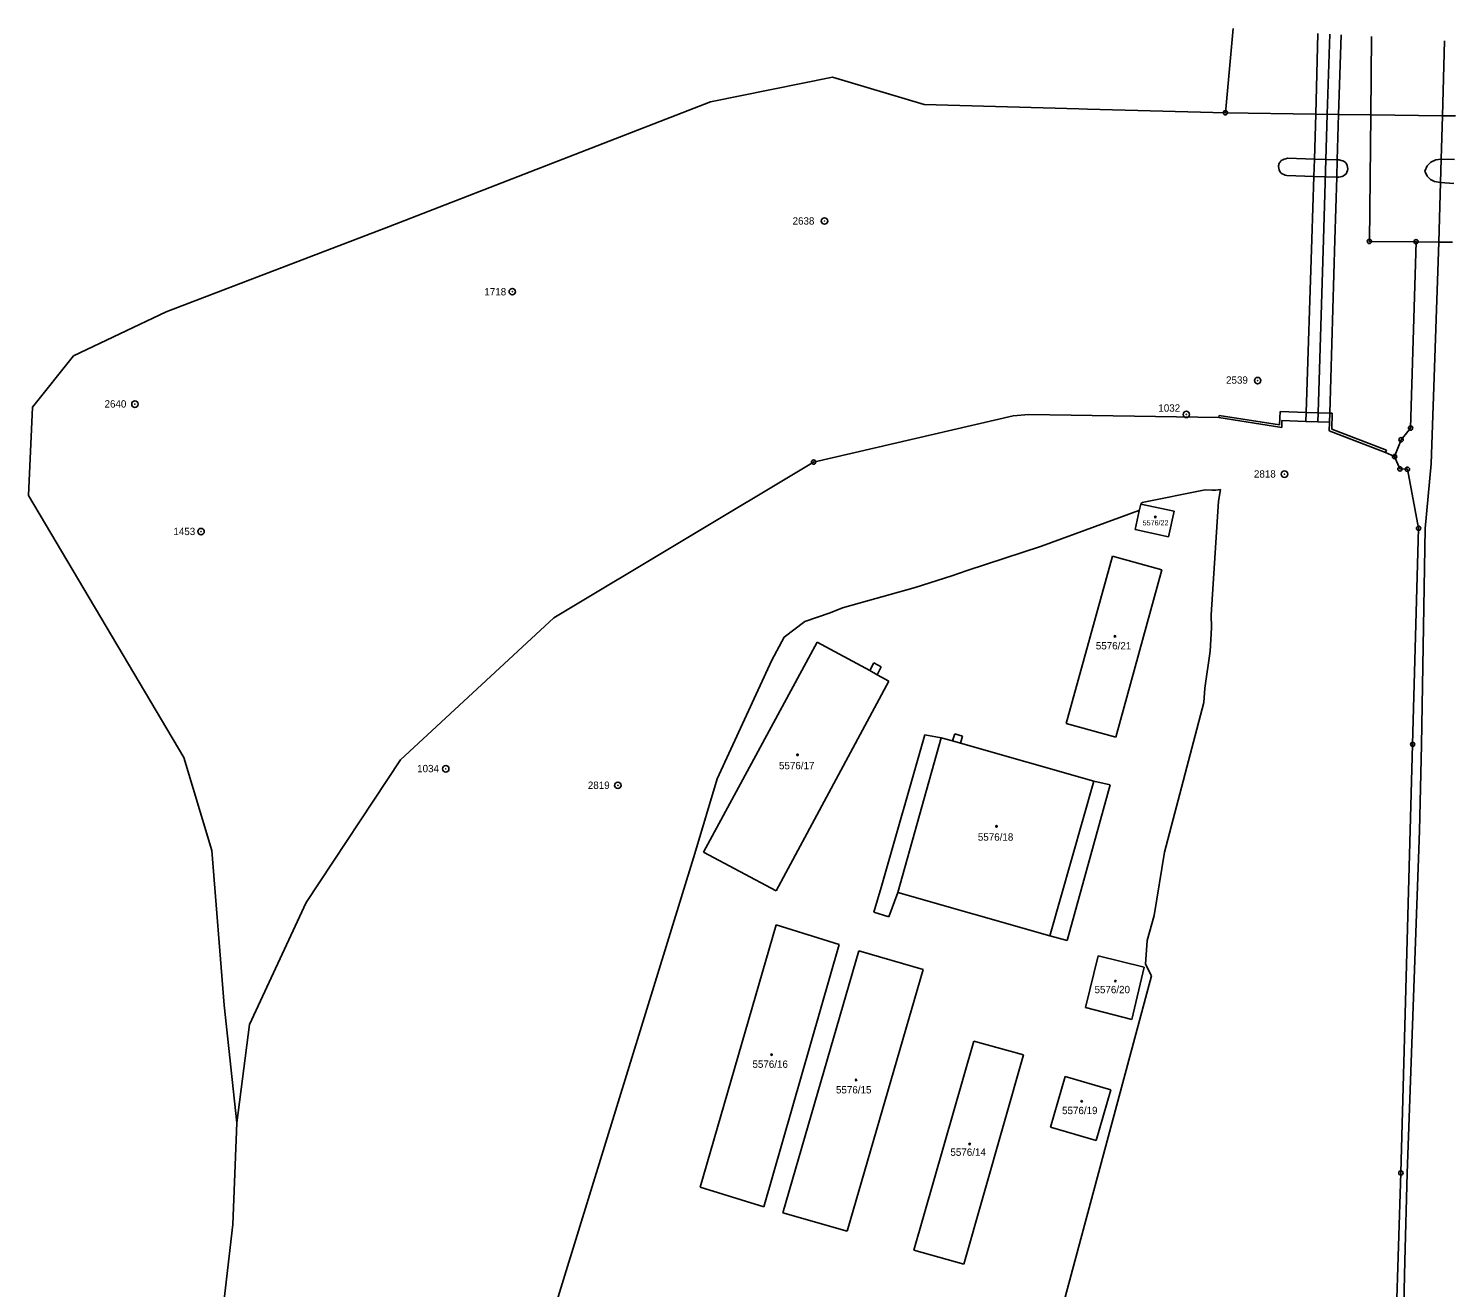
# Model space of a CAD drawing. Extents: x -825057 to -819383, y -1071633 to -1067888.
# Drawn here: x -820739.8 to -820409.1, y -1068180 to -1067888.2 of the extents above; entities that cross this region are included whole.
import ezdxf

# ---------------------------------------------------------------- set-up
doc = ezdxf.new("R2010")
doc.units = 0
for name, color, linetype in [('Vrstva 1', 7, 'Continuous'), ('Vrstva 10', 7, 'Continuous'), ('Vrstva 13', 7, 'Continuous'), ('Vrstva 17', 7, 'Continuous'), ('Vrstva 19', 7, 'Continuous'), ('Vrstva 24', 7, 'Continuous'), ('Vrstva 25', 7, 'Continuous'), ('Vrstva 4', 7, 'Continuous')]:
    doc.layers.add(name, color=color, linetype=linetype)

msp = doc.modelspace()

# ---------------------------------------------------------------- linework, layer by layer
at = {"layer": 'Vrstva 1'}
for p, q in [((-820462.39, -1067907.71), (-820460.6, -1067888.18)), ((-820428.72, -1067908.18), (-820428.52, -1067890.04)), ((-820418.2, -1067937.59), (-820419.46, -1067980.77)), ((-820419.46, -1067980.77), (-820421.67, -1067983.48)), ((-820421.67, -1067983.48), (-820423.18, -1067987.39)), ((-820421.94, -1067990.24), (-820423.18, -1067987.39)), ((-820420.21, -1067990.32), (-820421.94, -1067990.24)), ((-820420.21, -1067990.32), (-820417.63, -1068004.01)), ((-820463.52, -1067995.05), (-820464.61, -1067995.18)), ((-820463.98, -1067997.72), (-820463.52, -1067995.05)), ((-820481.69, -1067998.07), (-820482, -1067998.42)), ((-820467.11, -1067995.13), (-820481.69, -1067998.07)), ((-820465.53, -1067995.21), (-820467.11, -1067995.13)), ((-820465.71, -1068024.06), (-820463.98, -1067997.72)), ((-820464.61, -1067995.18), (-820465.53, -1067995.21)), ((-820482.47, -1067999.92), (-820505.06, -1068008.18)), ((-820482.35, -1067999.94), (-820483.35, -1068004.29)), ((-820482.35, -1067999.94), (-820482.47, -1067999.92)), ((-820482, -1067998.42), (-820482.35, -1067999.94)), ((-820474.31, -1068000.08), (-820482, -1067998.42)), ((-820475.58, -1068005.99), (-820474.31, -1068000.08)), ((-820483.35, -1068004.29), (-820475.58, -1068005.99)), ((-820417.63, -1068004.01), (-820418.99, -1068054.1)), ((-820505.06, -1068008.18), (-820522.24, -1068013.8)), ((-820488.59, -1068010.48), (-820499.28, -1068049.24)), ((-820477.14, -1068013.65), (-820488.59, -1068010.48)), ((-820522.24, -1068013.8), (-820525.77, -1068015.05)), ((-820487.81, -1068052.4), (-820477.14, -1068013.65)), ((-820534.33, -1068017.7), (-820551.15, -1068022.46)), ((-820525.77, -1068015.05), (-820534.33, -1068017.7)), ((-820553.98, -1068023.6), (-820559.86, -1068025.65)), ((-820551.15, -1068022.46), (-820553.98, -1068023.6)), ((-820465.65, -1068027.07), (-820465.71, -1068024.06)), ((-820559.86, -1068025.65), (-820564.66, -1068029.28)), ((-820465.96, -1068032.46), (-820465.65, -1068027.07)), ((-820557, -1068030.44), (-820583.34, -1068079.07)), ((-820564.66, -1068029.28), (-820567.5, -1068034.6)), ((-820544.81, -1068037.01), (-820557, -1068030.44)), ((-820567.5, -1068034.6), (-820580.2, -1068062.06)), ((-820467.2, -1068041.07), (-820465.96, -1068032.46)), ((-820543.87, -1068035.22), (-820544.81, -1068037.01)), ((-820542.16, -1068036.13), (-820543.87, -1068035.22)), ((-820543.14, -1068037.98), (-820542.16, -1068036.13)), ((-820540.43, -1068039.42), (-820543.14, -1068037.98)), ((-820566.56, -1068088.07), (-820540.43, -1068039.42)), ((-820467.37, -1068044.4), (-820467.2, -1068041.07)), ((-820476.52, -1068079.06), (-820467.37, -1068044.4)), ((-820499.28, -1068049.24), (-820487.81, -1068052.4)), ((-820532.08, -1068051.86), (-820542.16, -1068087.27)), ((-820528.28, -1068052.61), (-820532.08, -1068051.86)), ((-820525.63, -1068053.29), (-820528.28, -1068052.61)), ((-820525.14, -1068051.64), (-820525.63, -1068053.29)), ((-820523.33, -1068052.16), (-820525.14, -1068051.64)), ((-820523.8, -1068053.8), (-820523.33, -1068052.16)), ((-820492.86, -1068062.59), (-820523.8, -1068053.8)), ((-820418.99, -1068054.1), (-820421.73, -1068153.42)), ((-820580.2, -1068062.06), (-820585.41, -1068079.35)), ((-820499.07, -1068099.54), (-820489.07, -1068063.49)), ((-820489.07, -1068063.49), (-820492.86, -1068062.59)), ((-820585.41, -1068079.35), (-820626.81, -1068213.86)), ((-820583.34, -1068079.07), (-820566.56, -1068088.07)), ((-820478.94, -1068093.77), (-820476.52, -1068079.06)), ((-820542.16, -1068087.27), (-820543.92, -1068092.98)), ((-820540.42, -1068094.1), (-820538.33, -1068088.44)), ((-820538.33, -1068088.44), (-820503.13, -1068098.46)), ((-820543.92, -1068092.98), (-820540.42, -1068094.1)), ((-820480.51, -1068099.58), (-820478.94, -1068093.77)), ((-820566.56, -1068095.92), (-820584.13, -1068156.72)), ((-820551.95, -1068100.5), (-820566.56, -1068095.92)), ((-820569.35, -1068161.32), (-820551.95, -1068100.5)), ((-820503.13, -1068098.46), (-820499.07, -1068099.54)), ((-820480.9, -1068105), (-820480.51, -1068099.58)), ((-820547.35, -1068101.96), (-820564.97, -1068162.7)), ((-820532.49, -1068106.3), (-820547.35, -1068101.96)), ((-820491.9, -1068103.08), (-820494.82, -1068115.08)), ((-820481.22, -1068105.74), (-820491.9, -1068103.08)), ((-820550.06, -1068166.95), (-820532.49, -1068106.3)), ((-820484.11, -1068117.86), (-820481.22, -1068105.74)), ((-820479.5, -1068107.74), (-820480.9, -1068105)), ((-820526.3, -1068281.47), (-820479.5, -1068107.74)), ((-820494.82, -1068115.08), (-820484.11, -1068117.86)), ((-820520.73, -1068122.9), (-820534.58, -1068171.3)), ((-820509.19, -1068126.05), (-820520.73, -1068122.9)), ((-820523.02, -1068174.59), (-820509.19, -1068126.05)), ((-820499.54, -1068131.04), (-820502.9, -1068142.82)), ((-820488.93, -1068134.17), (-820499.54, -1068131.04)), ((-820492.33, -1068145.89), (-820488.93, -1068134.17)), ((-820502.9, -1068142.82), (-820492.33, -1068145.89)), ((-820421.73, -1068153.42), (-820424.47, -1068237.64)), ((-820584.13, -1068156.72), (-820569.35, -1068161.32)), ((-820564.97, -1068162.7), (-820550.06, -1068166.95)), ((-820534.58, -1068171.3), (-820523.02, -1068174.59))]:
    msp.add_line(p, q, dxfattribs=at)
at = {"layer": 'Vrstva 10'}
for p, q in [((-820438.18, -1067889.48), (-820438.79, -1067908.04)), ((-820439.69, -1067937.07), (-820438.79, -1067908.04)), ((-820439.69, -1067937.07), (-820438.79, -1067908.04)), ((-820439.69, -1067937.07), (-820440.93, -1067977.23)), ((-820439.69, -1067937.07), (-820440.93, -1067977.23)), ((-820440.93, -1067977.23), (-820441, -1067979.32)), ((-820440.93, -1067977.23), (-820441, -1067979.32))]:
    msp.add_line(p, q, dxfattribs=at)
at = {"layer": 'Vrstva 13'}
for p, q in [((-820581.71, -1067905.15), (-820553.46, -1067899.42)), ((-820553.46, -1067899.42), (-820532.23, -1067905.78)), ((-820656.38, -1067934.11), (-820581.71, -1067905.15)), ((-820532.23, -1067905.78), (-820496.37, -1067906.77)), ((-820496.37, -1067906.77), (-820494.38, -1067906.83)), ((-820494.38, -1067906.83), (-820462.39, -1067907.71)), ((-820462.39, -1067907.71), (-820441.44, -1067908)), ((-820441.44, -1067908), (-820436.15, -1067908.08)), ((-820436.15, -1067908.08), (-820428.72, -1067908.18)), ((-820428.72, -1067908.18), (-820429.03, -1067937.51)), ((-820707.91, -1067953.84), (-820656.38, -1067934.11)), ((-820429.03, -1067937.51), (-820418.2, -1067937.59)), ((-820418.2, -1067937.59), (-820412.91, -1067937.67)), ((-820412.91, -1067937.67), (-820411.8, -1067937.69)), ((-820411.8, -1067937.69), (-820409.78, -1067937.72)), ((-820729.43, -1067964.06), (-820707.91, -1067953.84)), ((-820738.88, -1067975.9), (-820729.43, -1067964.06)), ((-820739.82, -1067996.42), (-820738.88, -1067975.9)), ((-820703.86, -1068057.11), (-820739.82, -1067996.42)), ((-820697.37, -1068078.67), (-820703.86, -1068057.11)), ((-820694.5, -1068114.54), (-820697.37, -1068078.67)), ((-820691.55, -1068141.8), (-820694.5, -1068114.54)), ((-820692.48, -1068165.36), (-820691.55, -1068141.8)), ((-820696.07, -1068196.5), (-820692.48, -1068165.36))]:
    msp.add_line(p, q, dxfattribs=at)
at = {"layer": 'Vrstva 24'}
for centre, radius in [((-820462.39, -1067907.71), 0.5), ((-820462.39, -1067907.71), 0.5), ((-820462.39, -1067907.71), 0.5), ((-820462.39, -1067907.71), 0.0327), ((-820462.39, -1067907.71), 0.0327), ((-820462.39, -1067907.71), 0.0327), ((-820555.32, -1067932.79), 0.75), ((-820555.32, -1067932.79), 0.75), ((-820555.32, -1067932.79), 0.0327), ((-820555.32, -1067932.79), 0.0327), ((-820429.03, -1067937.51), 0.5), ((-820429.03, -1067937.51), 0.5), ((-820429.03, -1067937.51), 0.5), ((-820429.03, -1067937.51), 0.5), ((-820429.03, -1067937.51), 0.0327), ((-820429.03, -1067937.51), 0.0327), ((-820429.03, -1067937.51), 0.0327), ((-820429.03, -1067937.51), 0.0327), ((-820418.2, -1067937.59), 0.5), ((-820418.2, -1067937.59), 0.5), ((-820418.2, -1067937.59), 0.5), ((-820418.2, -1067937.59), 0.5), ((-820418.2, -1067937.59), 0.0327), ((-820418.2, -1067937.59), 0.0327), ((-820418.2, -1067937.59), 0.0327), ((-820418.2, -1067937.59), 0.0327), ((-820627.69, -1067949.17), 0.75), ((-820627.69, -1067949.17), 0.75), ((-820627.69, -1067949.17), 0.0327), ((-820627.69, -1067949.17), 0.0327), ((-820454.92, -1067969.78), 0.75), ((-820454.92, -1067969.78), 0.75), ((-820454.92, -1067969.78), 0.0327), ((-820454.92, -1067969.78), 0.0327), ((-820715.16, -1067975.23), 0.75), ((-820715.16, -1067975.23), 0.75), ((-820715.16, -1067975.23), 0.0327), ((-820715.16, -1067975.23), 0.0327), ((-820471.45, -1067977.62), 0.75), ((-820471.45, -1067977.62), 0.75), ((-820471.45, -1067977.62), 0.0327), ((-820471.45, -1067977.62), 0.0327), ((-820419.46, -1067980.77), 0.5), ((-820419.46, -1067980.77), 0.5), ((-820419.46, -1067980.77), 0.0327), ((-820419.46, -1067980.77), 0.0327), ((-820421.67, -1067983.48), 0.5), ((-820421.67, -1067983.48), 0.5), ((-820421.67, -1067983.48), 0.0327), ((-820421.67, -1067983.48), 0.0327), ((-820557.84, -1067988.65), 0.5), ((-820557.84, -1067988.65), 0.5), ((-820423.18, -1067987.39), 0.5), ((-820423.18, -1067987.39), 0.5), ((-820423.18, -1067987.39), 0.0327), ((-820423.18, -1067987.39), 0.0327), ((-820557.84, -1067988.65), 0.0327), ((-820557.84, -1067988.65), 0.0327), ((-820448.69, -1067991.48), 0.75), ((-820448.69, -1067991.48), 0.75), ((-820448.69, -1067991.48), 0.0327), ((-820448.69, -1067991.48), 0.0327), ((-820421.94, -1067990.24), 0.5), ((-820421.94, -1067990.24), 0.5), ((-820421.94, -1067990.24), 0.0327), ((-820421.94, -1067990.24), 0.0327), ((-820420.21, -1067990.32), 0.5), ((-820420.21, -1067990.32), 0.5), ((-820420.21, -1067990.32), 0.0327), ((-820420.21, -1067990.32), 0.0327), ((-820699.84, -1068004.78), 0.75), ((-820699.84, -1068004.78), 0.75), ((-820699.84, -1068004.78), 0.0327), ((-820699.84, -1068004.78), 0.0327), ((-820417.63, -1068004.01), 0.5), ((-820417.63, -1068004.01), 0.5), ((-820417.63, -1068004.01), 0.0327), ((-820417.63, -1068004.01), 0.0327), ((-820418.99, -1068054.1), 0.5), ((-820418.99, -1068054.1), 0.5), ((-820418.99, -1068054.1), 0.0327), ((-820418.99, -1068054.1), 0.0327), ((-820643.12, -1068059.77), 0.75), ((-820643.12, -1068059.77), 0.75), ((-820643.12, -1068059.77), 0.0327), ((-820643.12, -1068059.77), 0.0327), ((-820603.21, -1068063.59), 0.75), ((-820603.21, -1068063.59), 0.75), ((-820603.21, -1068063.59), 0.0327), ((-820603.21, -1068063.59), 0.0327), ((-820421.73, -1068153.42), 0.5), ((-820421.73, -1068153.42), 0.5), ((-820421.73, -1068153.42), 0.0327), ((-820421.73, -1068153.42), 0.0327)]:
    msp.add_circle(centre, radius, dxfattribs=at)
at = {"layer": 'Vrstva 25'}
for centre in [(-820478.64, -1068001.4), (-820478.64, -1068001.4), (-820487.98, -1068029.04), (-820487.98, -1068029.04), (-820561.58, -1068056.52), (-820561.58, -1068056.52), (-820515.45, -1068073.11), (-820515.45, -1068073.11), (-820487.88, -1068108.97), (-820487.88, -1068108.97), (-820567.59, -1068126.01), (-820567.59, -1068126.01), (-820547.99, -1068131.88), (-820547.99, -1068131.88), (-820495.7, -1068136.8), (-820495.7, -1068136.8), (-820521.68, -1068146.73), (-820521.68, -1068146.73)]:
    msp.add_circle(centre, 0.175, dxfattribs=at)
at = {"layer": 'Vrstva 4'}
for p, q in [((-820441.44, -1067908), (-820440.95, -1067889.32)), ((-820436.15, -1067908.08), (-820435.6, -1067889.63)), ((-820412.08, -1067908.41), (-820411.59, -1067891.03)), ((-820441.78, -1067918.45), (-820441.44, -1067908)), ((-820436.15, -1067908.08), (-820436.46, -1067918.61)), ((-820428.72, -1067908.18), (-820412.08, -1067908.41)), ((-820412.36, -1067918.43), (-820412.08, -1067908.41)), ((-820412.08, -1067908.41), (-820409.07, -1067908.45)), ((-820447.99, -1067918.26), (-820441.78, -1067918.45)), ((-820441.91, -1067922.45), (-820441.78, -1067918.45)), ((-820441.78, -1067918.45), (-820436.46, -1067918.61)), ((-820436.46, -1067918.61), (-820436.58, -1067922.63)), ((-820436.46, -1067918.61), (-820435.99, -1067918.63)), ((-820414.8, -1067919.17), (-820413.65, -1067918.62)), ((-820413.65, -1067918.62), (-820412.36, -1067918.43)), ((-820412.52, -1067923.88), (-820412.36, -1067918.43)), ((-820412.36, -1067918.43), (-820409.31, -1067918.56)), ((-820441.91, -1067922.45), (-820448.14, -1067922.25)), ((-820416.16, -1067921.22), (-820415.59, -1067920)), ((-820416.16, -1067921.22), (-820415.61, -1067922.43)), ((-820415.59, -1067920), (-820414.8, -1067919.17)), ((-820442.37, -1067936.96), (-820441.91, -1067922.45)), ((-820436.58, -1067922.63), (-820441.91, -1067922.45)), ((-820436.58, -1067922.63), (-820437.01, -1067937.18)), ((-820436.14, -1067922.65), (-820436.58, -1067922.63)), ((-820415.61, -1067922.43), (-820414.83, -1067923.17)), ((-820414.83, -1067923.17), (-820413.9, -1067923.65)), ((-820413.9, -1067923.65), (-820412.52, -1067923.88)), ((-820412.91, -1067937.67), (-820412.52, -1067923.88)), ((-820412.52, -1067923.88), (-820409.45, -1067924.07)), ((-820443.66, -1067977.15), (-820442.37, -1067936.96)), ((-820437.01, -1067937.18), (-820438.2, -1067977.32)), ((-820412.91, -1067937.67), (-820414.72, -1067989.08)), ((-820557.84, -1067988.65), (-820511.61, -1067977.91)), ((-820511.61, -1067977.91), (-820507.99, -1067977.62)), ((-820507.99, -1067977.62), (-820463.92, -1067978.31)), ((-820463.92, -1067978.31), (-820463.85, -1067977.86)), ((-820449.34, -1067980.62), (-820463.92, -1067978.31)), ((-820463.85, -1067977.86), (-820449.83, -1067980.06)), ((-820449.83, -1067980.06), (-820449.7, -1067976.97)), ((-820449.7, -1067976.97), (-820443.66, -1067977.15)), ((-820443.73, -1067979.24), (-820443.66, -1067977.15)), ((-820443.66, -1067977.15), (-820438.2, -1067977.32)), ((-820438.2, -1067977.32), (-820438.26, -1067979.41)), ((-820438.2, -1067977.32), (-820437.65, -1067977.33)), ((-820437.65, -1067977.33), (-820437.71, -1067981)), ((-820449.29, -1067979.06), (-820449.34, -1067980.62)), ((-820443.73, -1067979.24), (-820449.29, -1067979.06)), ((-820438.26, -1067979.41), (-820443.73, -1067979.24)), ((-820438.32, -1067981.43), (-820438.26, -1067979.41)), ((-820425.25, -1067986.42), (-820438.32, -1067981.43)), ((-820437.71, -1067981), (-820425.04, -1067985.89)), ((-820425.04, -1067985.89), (-820425.25, -1067986.42)), ((-820425.25, -1067986.42), (-820423.18, -1067987.39)), ((-820618.08, -1068024.74), (-820557.84, -1067988.65)), ((-820414.72, -1067989.08), (-820416.1, -1068004.04)), ((-820416.1, -1068004.04), (-820416.98, -1068054.17)), ((-820653.59, -1068057.67), (-820618.08, -1068024.74)), ((-820544.81, -1068037.01), (-820543.14, -1068037.98)), ((-820538.33, -1068088.44), (-820528.28, -1068052.61)), ((-820525.63, -1068053.29), (-820523.8, -1068053.8)), ((-820416.98, -1068054.17), (-820417.42, -1068074.15)), ((-820675.44, -1068090.73), (-820653.59, -1068057.67)), ((-820503.13, -1068098.46), (-820492.86, -1068062.59)), ((-820417.42, -1068074.15), (-820420.27, -1068153.46)), ((-820688.62, -1068118.99), (-820675.44, -1068090.73)), ((-820691.55, -1068141.8), (-820688.62, -1068118.99)), ((-820420.27, -1068153.46), (-820420.81, -1068173.9)), ((-820420.81, -1068173.9), (-820421.91, -1068226.33))]:
    msp.add_line(p, q, dxfattribs=at)
for points in [[(-820448.14, -1067922.25), (-820449.52, -1067921.59), (-820450.08, -1067920.18), (-820449.91, -1067919.42), (-820449.44, -1067918.8), (-820447.99, -1067918.26)], [(-820435.99, -1067918.63), (-820434.56, -1067919.24), (-820434.04, -1067920.71), (-820434.69, -1067922.1), (-820436.14, -1067922.65)]]:
    msp.add_spline(points, degree=3, dxfattribs=at)

# ---------------------------------------------------------------- texts
at = {"layer": 'Vrstva 17'}
for s, p in [('2638', (-820562.722, -1067933.62)), ('2638', (-820562.722, -1067933.62)), ('1718', (-820634.163, -1067950.04)), ('1718', (-820634.163, -1067950.04)), ('2539', (-820462.244, -1067970.5)), ('2539', (-820462.244, -1067970.5)), ('2640', (-820722.204, -1067976.03)), ('2640', (-820722.204, -1067976.03)), ('1032', (-820477.942, -1067976.98)), ('1032', (-820477.942, -1067976.98)), ('2818', (-820455.781, -1067992.26)), ('2818', (-820455.781, -1067992.26)), ('1453', (-820706.241, -1068005.59)), ('1453', (-820706.241, -1068005.59)), ('1034', (-820649.742, -1068060.55)), ('1034', (-820649.742, -1068060.55)), ('2819', (-820610.176, -1068064.41)), ('2819', (-820610.176, -1068064.41))]:
    msp.add_text(s, height=1.7, dxfattribs=at).set_placement(p)
at = {"layer": 'Vrstva 19'}
for s, height, p in [('5576/22', 1.2, (-820481.586, -1068003.34)), ('5576/22', 1.2, (-820481.586, -1068003.34)), ('5576/21', 1.7, (-820492.43, -1068032.09)), ('5576/21', 1.7, (-820492.43, -1068032.09)), ('5576/17', 1.7, (-820565.87, -1068059.86)), ('5576/17', 1.7, (-820565.87, -1068059.86)), ('5576/18', 1.7, (-820519.773, -1068076.42)), ('5576/18', 1.7, (-820519.773, -1068076.42)), ('5576/20', 1.7, (-820492.732, -1068111.77)), ('5576/20', 1.7, (-820492.732, -1068111.77)), ('5576/16', 1.7, (-820572.016, -1068129.06)), ('5576/16', 1.7, (-820572.016, -1068129.06)), ('5576/15', 1.7, (-820552.657, -1068135)), ('5576/15', 1.7, (-820552.657, -1068135)), ('5576/19', 1.7, (-820500.256, -1068139.8)), ('5576/19', 1.7, (-820500.256, -1068139.8)), ('5576/14', 1.7, (-820526.136, -1068149.46)), ('5576/14', 1.7, (-820526.136, -1068149.46))]:
    msp.add_text(s, height=height, dxfattribs=at).set_placement(p)

doc.saveas('drawing.dxf')
